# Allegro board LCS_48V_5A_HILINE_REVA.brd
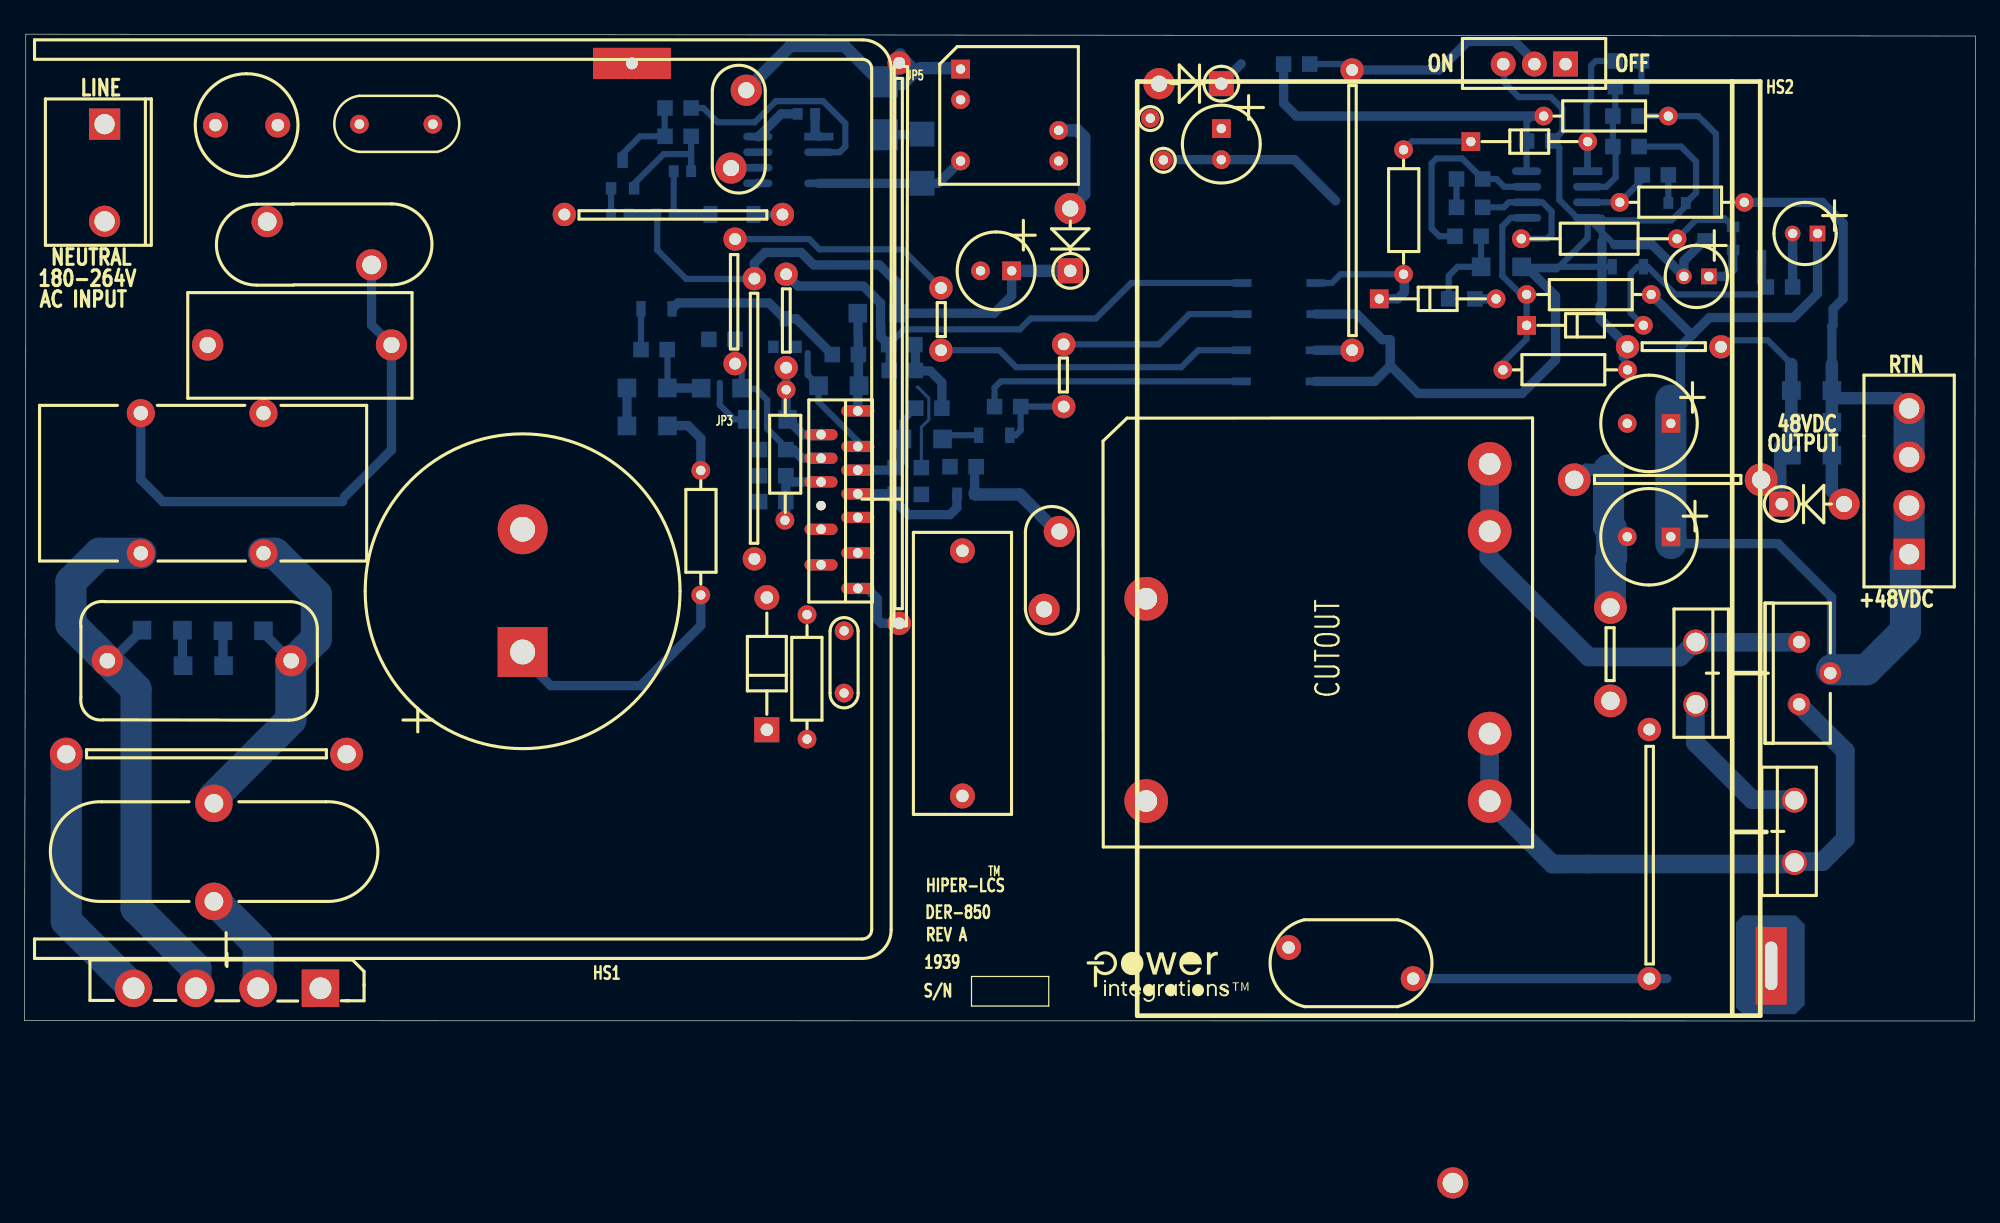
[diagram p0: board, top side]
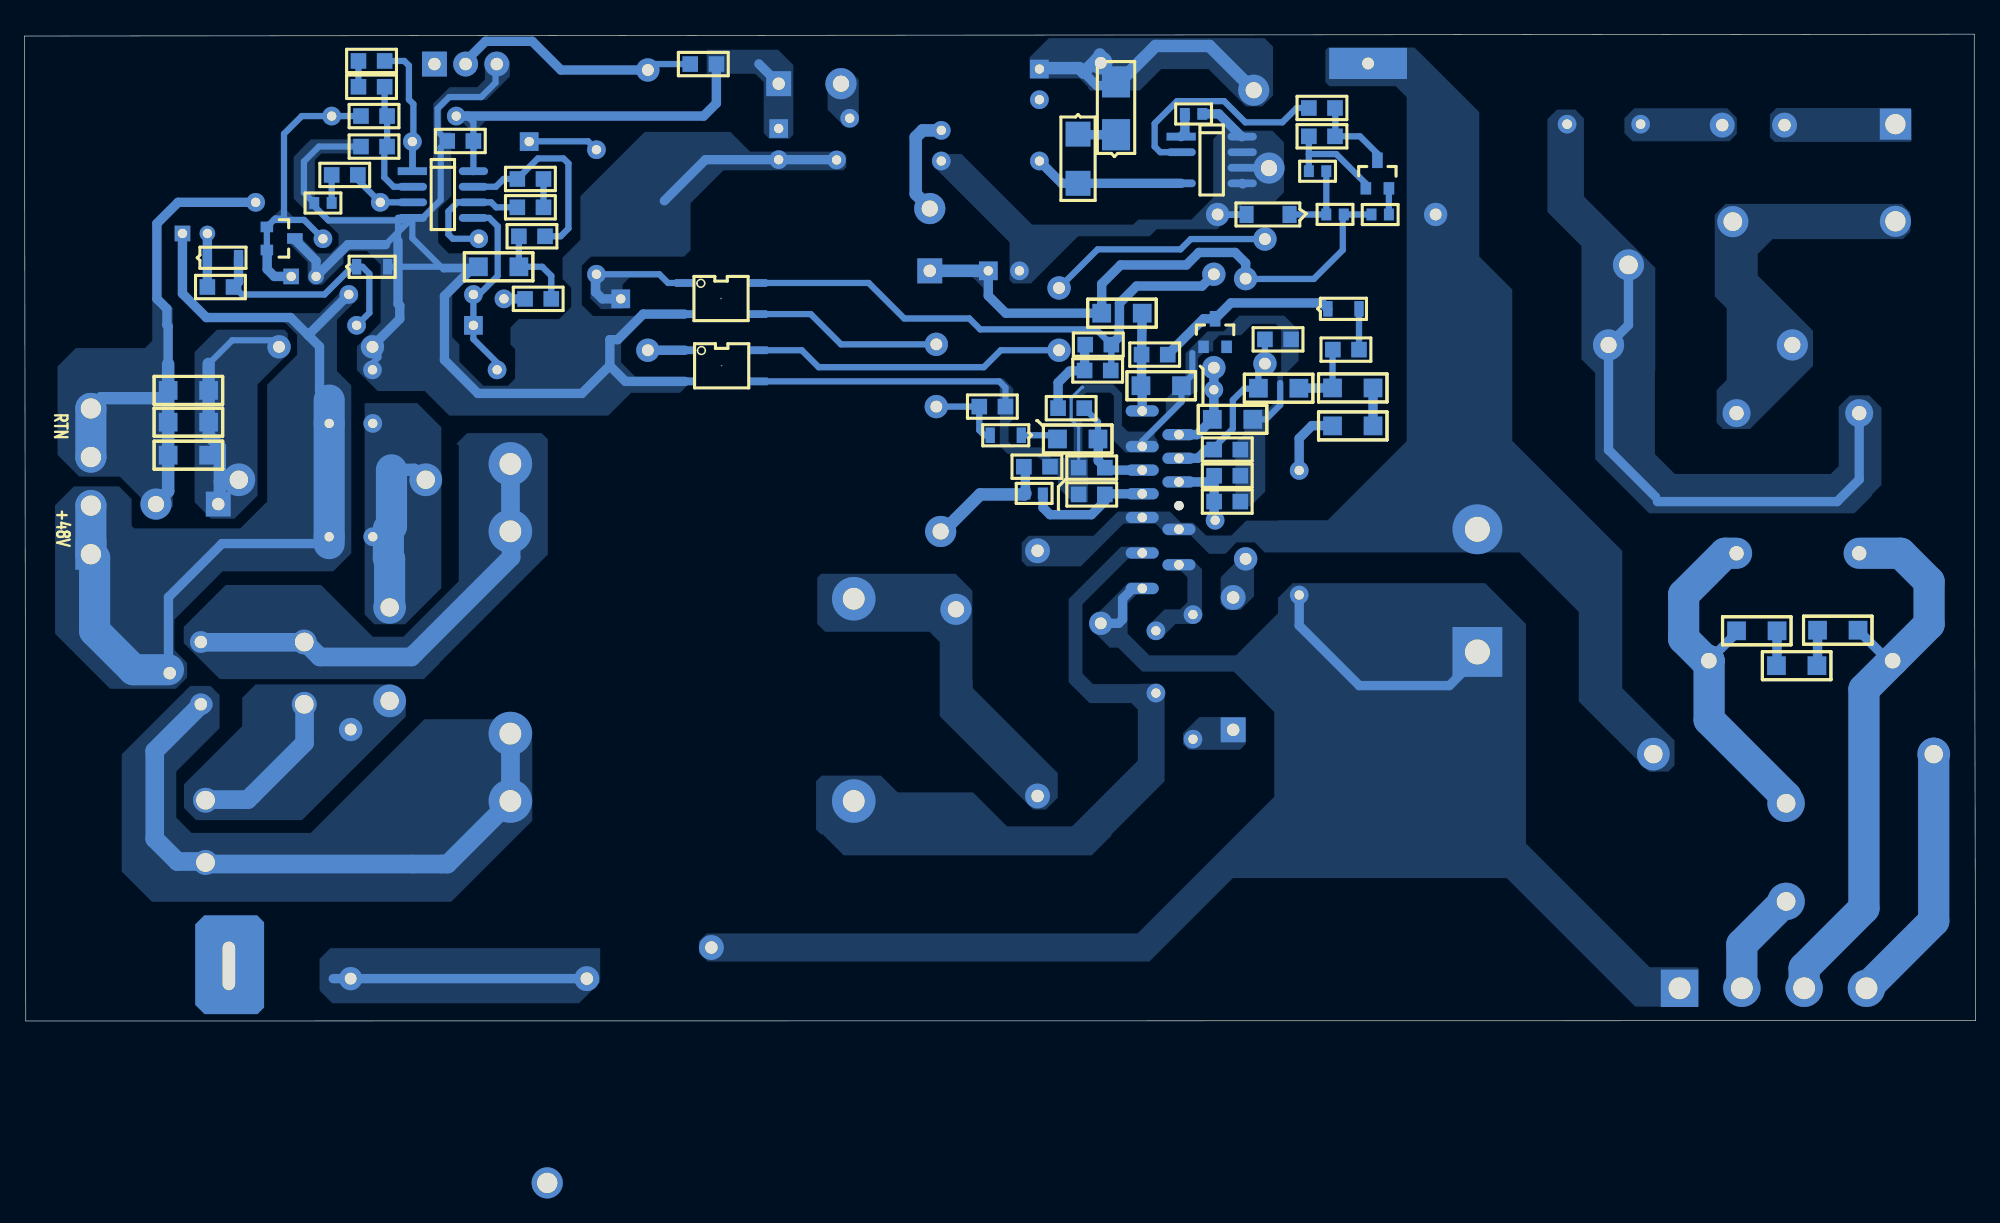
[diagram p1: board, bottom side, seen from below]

Outline 159.08 x 80.49 mm; copper layers: TOP, BOTTOM. Coordinates in mm from the lower left corner of the outline.
Outline path: 0,0.03 0.1,55.09 0.1,80.49 159.08,80.34 158.98,0 0,0.03

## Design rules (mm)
constraint set DEFAULT: min track width 0.508

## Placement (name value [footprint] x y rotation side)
BR1  GBU8J  [PIDAXBRIDGEGBU8]  24.13 2.67 180 top
C1  220 nF  [PINPXCAPRAD720X340590040]  29.92 55.14 180 top
C2  470 nF  [PINPCAPRAD760X380590050]  21.74 29.39 180 top
C3  270 uF  [PIPOLCAPCLYD948LS394080]  40.59 30.1 90 top
C6  330 nF  [PINPCAPRAD200X100200030]  66.83 31.83 270 top
C7  330 nF  [PISMC0805]  70.51 53.06 0 bottom
C8  22 nF  [PISMC0805]  62.08 46.61 180 bottom
C9  4.7 nF  [PISMC0805]  62.08 44.48 180 bottom
C10  1 uF  [PISMC1206]  62.23 49.07 180 bottom
C11  1 uF  [PISMC1206]  68.05 51.82 180 bottom
C12  4.7 nF  [PISMC0805]  70.99 45.14 0 bottom
C13  1 nF  [PISMC0805]  70.99 42.95 0 bottom
C14  0.039 uF  [PINPCAP23X8X20MMLSD040]  76.48 38.35 270 top
C15  47 pF  [PINPCAPRAD370X156250040]  84.4 39.93 270 top
C16  2.2 nF  [PINPYCAPRAD540X290LS400040]  103.07 5.99 0 top
C20  1.5 uF  [PISMC1206]  122.07 61.52 180 bottom
C21  150 nF  [PISMC0805]  118.9 68.68 180 bottom
C23  100 nF  [PISMC0805]  122.48 71.78 0 bottom
C24  22 nF  [PISMC0805]  131.85 76.2 180 bottom
C25  10 uF  [PIPOLCAPCLYD200LS80030]  137.34 60.73 180 top
C27  4.7 nF  [PINPCAPRAD370X156250040]  58.88 75.92 270 top
C28  1 uF  [PISMC0603]  64.47 73.99 180 bottom
C29  150 uF  [PIPOLCAPCYLD250LS100030]  97.59 72.8 270 top
C30  150 uF  [PIPOLCAPCYLD250LS100030]  80.49 61.19 180 top
C31  10 nF  [PISMC0805]  54.36 72.16 180 bottom
C35  27 uF  [PIPOLCAPCLYD320LS140030]  134.24 48.74 180 top
C37  68 nF  [PISMC0805]  134.04 69.01 180 bottom
C38  1 uF  [PIPOLCAPCLYD200LS80030]  146.2 64.24 180 top
C39  27 uF  [PIPOLCAPCLYD320LS140030]  134.24 39.5 180 top
D1  BAV19WS  [PISMSOD323]  77.8 47.78 0 bottom
D2  BAV19WS  [PISMSOD323]  52.81 58.09 180 bottom
D3  UF4005  [PIDAX475X125040DO41]  60.53 23.75 90 top
D6  1N4148  [PIDAX375X070030DO35]  117.93 71.73 0 top
D7  1N4148  [PIDAX375X070030DO35]  110.46 58.9 0 top
D8  1N4002-E3/54  [PIDV200X110X040DO41]  143.28 42.16 0 top
D9  UF4003  [PIDV200X110X040DO41]  97.59 76.45 180 top
D10  UF4003  [PIDV200X110X040DO41]  85.27 61.19 90 top
D11  US1J  [PISMDSMA]  73.18 72.34 270 bottom
D12  MBR2060CT  [PIDVTO2203VF1]  144.7 28.37 90 top
D13  MBR1060  [PIDVT0220ACREVA]  136.27 25.83 90 top
D14  MBR1060  [PIDVT0220ACREVA]  144.32 18.01 270 top
D15  BAV19WS  [PISMSOD323]  144.17 62.26 180 bottom
D16  BAV19WS  [PISMSOD323]  132 61.52 180 bottom
D17  1N4148  [PIDAX375X070030DO35]  122.48 56.74 0 top
F1  5 A  [PI_TR5_SUBMIN_FUSE]  15.57 73.08 0 top
HS1  HEATSINK, W/PEM NUT AND EYELET, PI CUST  [PI_HS_DER447_BRIDGE_ESIP]  0.81 80.04 270 top
HS2  HEATSINK,  FAB, DER850, PI CUST  [PI_HS_1P_DER850]  141.53 0.43 0 top
J1  CON3  [PI_HDR_3PIN_156_LOCK]  6.53 73.15 180 top
J2  CON4  [PI_HDR_4PIN]  153.67 38.07 0 top
J5  FL2  [PI_HOLE_30AWG]  92.86 70.23 0 top
J6  FL1  [PI_HOLE_30AWG]  91.8 73.63 0 top
JP1  J  [PI_JUMPER700]  44.02 65.79 0 top
JP2  J  [PI_JUMPER400]  57.94 53.62 90 top
JP3  J  [PI_JUMPER900]  59.51 60.55 270 top
JP4  J  [PI_JUMPER300]  62.1 60.91 270 top
JP5  J  [PI_JUMPER1800]  71.32 32.44 90 top
JP6  J  [PI_JUMPER200]  74.73 59.79 270 top
JP7  J  [PI_JUMPER200]  84.73 50.11 90 top
JP8  J  [PI_JUMPER900]  108.25 54.71 90 top
JP9  J  [PI_JUMPER300]  130.71 54.99 0 top
JP10  J  [PI_JUMPER600-18AWG-SLD]  126.36 44.15 0 top
JP11  J  [PI_JUMPER300-18AWG-SLD]  129.31 26.11 90 top
JP12  J  [PI_JUMPER800]  132.49 3.45 90 top
JP13  J  [PI_JUMPER900-18AWG-SLD]  3.4 21.77 0 top
L1  9 mH  [PI_IND_4P_500X1050LS450D46]  9.48 38.15 90 top
L2  100 uH  [PI2P455X1062LS315D60]  15.44 9.75 90 top
NOREF  -  []  0 0.03 0 top
NOREF#2  -  []  0 0.03 90 top
NOREF#3  -  []  -228.17 -156.46 0 top
NOREF#4  -  []  -150.35 42.55 0 top
NOREF#5  -  []  86.61 6.12 0 top
Q1  MMBT4403  [PISMSOT23132]  47.83 67.92 180 bottom
R1  680 k  [PISMR1206]  9.58 31.88 0 bottom
R2  680 k  [PISMR1206]  12.93 28.98 0 bottom
R3  680 k  [PISMR1206]  16.18 31.83 0 bottom
R4  301 k  [PI14WRESD100LS400D030]  55.14 44.91 270 top
R5  287 k  [PISMR1206]  52.43 48.54 180 bottom
R6  287 k  [PISMR1206]  49.12 51.64 0 bottom
R8  4.99 k  [PISMR0805]  52.4 54.76 180 bottom
R9  10.0 k  [PISMR1206]  55.17 51.61 0 bottom
R10  10 k  [PISMR0805]  57.94 55.6 180 bottom
R11  3.3 k  [PISMR0805]  65.86 54.36 0 bottom
R12  82.5 k  [PISMR0805]  70.46 55.17 0 bottom
R13  5.76 k  [PISMR0805]  74.8 49.99 180 bottom
R14  2.2 k  [PISMR1206]  74.85 47.47 180 bottom
R15  4.7 k  [PISMR0805]  81.23 50.11 180 bottom
R16  6.81 k  [PI14WRESD100LS400D030#2]  62 53.54 270 top
R17  130 k  [PISMR0805]  62.08 42.37 180 bottom
R18  4.7  [PISMR1206]  71.25 57.73 180 bottom
R19  2.2  [PI14WRESD100LS400D030]  63.8 22.99 90 top
R20  220  [PISMR0603]  76.05 43.03 0 bottom
R21  39  [PISMR0805]  75.46 45.21 0 bottom
R22  1 k  [PISMR0805]  118.26 58.9 180 bottom
R23  1.3 k  [PI14WRESD100LS400D030]  112.45 71.07 270 top
R24  182 k  [PI14WRESD100LS500D030#2]  132.64 59.26 180 top
R26  10 k  [PISMR0805]  116.76 66.37 0 bottom
R27  10.0 k  [PI14WRESD100LS400D030]  120.55 53.11 0 top
R28  22 k  [PI14WRESD100LS500D030]  134.75 63.8 180 top
R29  3.3 k  [PI14WVRESD100LS100D030]  123.88 73.81 0 top
R30  22 k  [PISMR0805]  129.72 78.31 0 bottom
R31  249 k  [PISMR0805]  129.51 73.81 0 bottom
R32  5.11 k  [PISMR0805]  129.51 71.32 0 bottom
R33  5.1 k  [PI14WRESD100LS400D030]  130.07 66.78 0 top
R34  0.03  [PISMR1206]  144.07 46.15 0 bottom
R35  0.03  [PISMR1206]  144.07 51.43 0 bottom
R36  100  [PISMR0603]  49.25 65.79 180 bottom
R37  1 k  [PISMR0603]  51.51 65.79 0 bottom
R38  15 k  [PISMR0805]  52.22 74.47 0 bottom
R39  10 k  [PISMR0805]  102.67 78.05 0 bottom
R40  1 k  [PISMR0603]  54.36 69.32 180 bottom
R42  0.03  [PISMR1206]  144.07 48.84 0 bottom
R43  1 k  [PISMR0805]  118.77 64.01 180 bottom
R44  510  [PISMR0603]  135.46 66.73 180 bottom
R45  100 k  [PISMR0805]  144.17 59.87 180 bottom
RT1  2.5  [PI_RAD180X395LS235D031]  27.3 73.15 0 top
RV1  320 Vac  [PIDISC675X225LS335X140040]  28.3 61.67 180 top
SW1  SPDT SLIDE  [PI_SWITCH_SPDT_SLIDE_PCBM_1]  125.65 78.05 90 top
T1  ETD34  [PI_XFRMR_DER850_LLC]  91.44 45.47 0 top
T2  EE10  [PI_XFRMR_DER850_BIAS]  76.33 77.65 0 top
U1  LCS708HG  [PI_IC_ESIP16-13_OVAL_SLOT]  67.94 49.76 270 top
U2  LNK302D  [PISMSO8DNSHORT5678]  64.77 72.14 270 bottom
U3  LM431AIM3  [PISMSOT23123]  139.32 62.89 270 bottom
U4  PC357A  [PI_4_SMD]  102.29 58.93 270 bottom
U5  LM358D  [PISMSO8]  127.46 69.32 270 bottom
U6  PC357A  [PI_4_SMD]  102.23 53.44 270 bottom
VR1  BZX84C5V1LT1G  [PISMSOT23123]  61.06 54.99 180 bottom
VR2  MMSZ5242B-7-F  [PI_SM_SOD-123_12]  55.93 65.79 0 bottom
VR3  SMAJ150A-13-F  [PISMDO214AC12]  70.08 72.29 90 bottom

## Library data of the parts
BR1 = DISCRETE BRIDGE_+~~-
C1 C6-C8 C10 C11 C14 C20 C21 C23 C24 C27 C28 C37 = CAP NP
C2 = CAP NP: tolerance: 20
C3 C35 C39 = CAP POL
C9 C12 C13 C31 = CAP NP: tolerance: 10
C15 = CAP NP: tolerance: 5
C16 = CAP NP: alternate symbols: (pinpycaprad540x290ls400040h)
C25 C38 = CAP POL: alternate symbols: (pipolcapclyd200ls80030h)
C29 C30 = CAP POL: tolerance: 20
D1 D2 D11 D15 D16 = DIODE
D3 = DIODE: alternate symbols: (pidax475x125040do41,pidax390x125040do41)
D6 D7 D17 = DIODE: alternate symbols: (pidax375x070030do35,pidv100x080x030do35)
D8-D10 = DIODE: alternate symbols: (pidax475x125040do41,pidv200x110x040do41wbead,pidax390x125040do41)
D12 = DS_DUAL_CK_A_AC: alternate symbols: (pidvto2203)
D13 D14 = DIODE SCHOTTKY
F1 = FUSE
HS1 = HS-PI_CUSTOM1
HS2 = hs_1P_DER850
J1 = CON3
J2 = CON4
J5 J6 = TERM_1Pin
JP1-JP13 = JUMPER_1
L1 = INDUCTOR_4P_REVB_0
L2 = INDUCTOR
Q1 = PNP_BEC
R1-R3 R10-R14 R17 R18 R20-R22 R26 R30-R32 R34-R40 R42 R43 R45 = R
R4 R19 R23 R28 = R: alternate symbols: (pi14wvresd100ls125d030,pi14wvresd100ls150d030,pi14wvresd100ls200d030,pi14wvresd100ls300d030,pi14wresd100ls400d030,pi14wresd100ls500d030)
R5 R6 R8 R9 R44 = R: tolerance: 1%
R15 = R: tolerance: 5%
R16 R24 R27 R29 = R: alternate symbols: (pi14wvresd100ls200d030,pi14wresd100ls400d030,pi14wresd100ls500d030)
R33 = R: alternate symbols: (pi14wvresd100ls125d030,pi14wvresd100ls150d030,pi14wvresd100ls200d030,pi14wvresd100ls300d030,pi14wresd100ls400d030,pi14wresd100ls500d030); tolerance: 1%
RT1 = THERMISTOR
RV1 = VARISTOR
SW1 = SW SLIDE-SPDT
T1 = BETD_34_DER850_LLC
T2 = BEE_10_DER850_Bias
U1 = LC_SWITCH_Rev03: alternate symbols: (pi_ic_esip16-13_socket_sl0t,pi_ic_esip16-13_oval_slot)
U2 = LNK30X_SO8_DN
U3 = TL431/SOT-23_CAR: tolerance: 2%
U4 U6 = OPTO_A_B
U5 = LM358
VR1 = DIODE_ZENERC2A1
VR2 VR3 = DIODE_ZENER

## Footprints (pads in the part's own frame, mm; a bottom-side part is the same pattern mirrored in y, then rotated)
PI2P455X1062LS315D60
  round 3.048 hole 1.524: 1(0,0) 2(8.001,0)
PI14WRESD100LS400D030
  round 1.524 hole 0.762: 1(0,0) 2(10.16,0)
PI14WRESD100LS400D030#2
  round 1.524 hole 0.762: 1(2.057,0.102) 2(12.7,0)
PI14WRESD100LS500D030
  round 1.524 hole 0.762: 1(0,0) 2(12.7,0)
PI14WRESD100LS500D030#2
  round 1.524 hole 0.762: 1(0,0) 2(10.16,0)
PI14WVRESD100LS100D030
  round 1.524 hole 0.762: 1(0,0) 2(10.16,0)
PI_4_SMD
  rect 0.635x1.524 smd: 1(-1.27,-2.997) 2(1.27,-2.997) 3(1.27,2.997) 4(-1.27,2.997)
PI_HDR_3PIN_156_LOCK
  rect 2.54x2.54 hole 1.651: 1(0,0)
  round 2.54 hole 1.651: 2(-109.931,86.36) 3(0,7.925)
PI_HDR_4PIN
  rect 2.54x2.54 hole 1.651: 1(0,0)
  round 2.54 hole 1.651: 2(0,3.962) 3(0,7.925) 4(0,11.887)
PI_HOLE_30AWG
  round 1.524 hole 0.762: 1(0,0)
PI_HS_1P_DER850
  rect 2.54x6.35 hole 1.016x3.962: 1(0.889,4.064)
PI_HS_DER447_BRIDGE_ESIP
  rect 2.54x6.35 hole 0.965: 1(1.93,48.717)
PI_IC_ESIP16-13_OVAL_SLOT
  oval 0.914x2.692 hole 0.787: 1(0,0) 3(1.93,-2.997) 4(2.896,0) 5(3.861,-2.997) 6(4.826,0) 7(5.791,-2.997) 8(6.756,0) 10(8.687,0) 11(9.652,-2.997) 13(11.582,0) 14(12.548,-2.997) 16(14.478,0)
  round 0.762 hole 0.762: 9(7.722,-2.997)
PI_IND_4P_500X1050LS450D46
  round 2.286 hole 1.168: 1(0,0) 2(11.43,-10) 3(11.43,0) 4(0,-10)
PI_JUMPER200
  round 1.905 hole 0.965: 1(0,0) 2(5.08,0)
PI_JUMPER300
  round 1.905 hole 0.965: 1(0,0) 2(7.62,0)
PI_JUMPER300-18AWG-SLD
  round 2.667 hole 1.499: 1(0,0) 2(7.62,0)
PI_JUMPER400
  round 1.905 hole 0.965: 1(0,0) 2(10.16,0)
PI_JUMPER600-18AWG-SLD
  round 2.667 hole 1.499: 1(0,0) 2(15.24,0)
PI_JUMPER700
  round 1.905 hole 0.965: 1(0,0) 2(17.78,0)
PI_JUMPER800
  round 1.905 hole 0.965: 1(0,0) 2(20.32,0)
PI_JUMPER900
  round 1.905 hole 0.965: 1(0,0) 2(22.86,0)
PI_JUMPER900-18AWG-SLD
  round 2.667 hole 1.499: 1(0,0) 2(22.86,0)
PI_JUMPER1800
  round 1.905 hole 0.965: 1(0,0) 2(45.72,0)
PI_RAD180X395LS235D031
  round 1.524 hole 0.787: 1(0,0) 2(5.994,0)
PI_SM_SOD-123_12
  rect 1.143x1.397 smd: 1(0,0) 2(3.505,0)
PI_SWITCH_SPDT_SLIDE_PCBM_1
  rect 2.032x2.032 hole 1.016: 1(0,0)
  round 2.032 hole 1.016: 2(0,2.54) 3(0,5.08)
PI_TR5_SUBMIN_FUSE
  round 2.032 hole 1.016: 1(0,0) 2(5.08,0)
PI_XFRMR_DER850_BIAS
  rect 1.524x1.524 hole 0.762: 1(0,0)
  round 1.524 hole 0.762: 2(0,-2.499) 4(0,-7.501) 5(8.001,-7.501) 6(8.001,-5.001)
PI_XFRMR_DER850_LLC
  round 3.556 hole 1.778: 3(0.025,-11.026) 6(0.025,-27.526) 7(28.026,-27.526) 8(28.026,-22.024) 11(28.026,-5.524) 12(28.026,-0.025)
PIDAX375X070030DO35
  rect 1.524x1.524 hole 0.762: 1(0,0)
  round 1.524 hole 0.762: 2(9.525,0)
PIDAX475X125040DO41
  rect 2.032x2.032 hole 1.016: 1(0,0)
  round 2.032 hole 1.016: 2(10.795,0)
PIDAXBRIDGEGBU8
  rect 3.048x3.048 hole 1.778: 1(0,0)
  round 3.048 hole 1.778: 2(5.08,0) 3(10.16,0) 4(15.24,0)
PIDISC675X225LS335X140040
  round 2.54 hole 1.524: 1(0,0) 2(8.509,-3.531)
PIDV200X110X040DO41
  rect 2.032x2.032 hole 1.016: 1(0,0)
  round 2.54 hole 1.321: 2(5.08,0)
PIDVT0220ACREVA
  round 2.032 hole 1.524: 1(5.08,0) 2(0,0)
PIDVTO2203VF1
  round 1.778 hole 1.016: 1(-2.54,0) 2(0,-2.54) 3(2.54,0)
PINPCAP23X8X20MMLSD040
  round 2.032 hole 1.016: 1(0,0) 2(20,0)
PINPCAPRAD200X100200030
  round 1.524 hole 0.762: 1(0,0) 2(5.08,0)
PINPCAPRAD370X156250040
  round 2.54 hole 1.321: 1(0,-0.025) 2(6.35,-1.27)
PINPCAPRAD760X380590050
  round 2.54 hole 1.27: 1(0,0) 2(14.986,0)
PINPXCAPRAD720X340590040
  round 2.54 hole 1.321: 1(0,0) 2(14.986,0)
PINPYCAPRAD540X290LS400040
  round 2.032 hole 1.016: 1(0,0) 2(10.16,-2.54)
PIPOLCAPCLYD200LS80030
  rect 1.27x1.27 hole 0.762: 1(0,0)
  round 1.27 hole 0.762: 2(2.032,0)
PIPOLCAPCLYD320LS140030
  rect 1.524x1.524 hole 0.762: 1(0,0)
  round 1.524 hole 0.762: 2(3.556,0)
PIPOLCAPCLYD948LS394080
  rect 4.064x4.064 hole 2.032: 1(0,-0.025)
  round 4.064 hole 2.032: 2(10.008,-0.025)
PIPOLCAPCYLD250LS100030
  rect 1.524x1.524 hole 0.762: 1(0,0)
  round 1.524 hole 0.762: 2(2.54,0)
PISMC0603
  rect 0.813x0.965 smd: 1(0,0) 2(1.422,0)
PISMC0805
  rect 1.27x1.27 smd: 1(0,0) 2(2.134,0)
PISMC1206
  rect 1.524x1.524 smd: 1(0,0) 2(3.302,0)
PISMDO214AC12
  rect 2.54x2.286 smd: 1(0,0) 2(4.318,0)
PISMDSMA
  rect 2.032x2.032 smd: 1(0,0) 2(4.013,0)
PISMR0603
  rect 0.813x0.965 smd: 1(0,0) 2(1.422,0)
PISMR0805
  rect 1.27x1.27 smd: 1(0,0) 2(2.134,0)
PISMR1206
  rect 1.524x1.524 smd: 1(0,0) 2(3.302,0)
PISMSO8
  rect 0.635x2.388 smd: 1(0,0)
  oval 0.635x2.388 smd: 2(1.27,0) 3(2.54,0) 4(3.81,0) 5(3.81,4.978) 6(2.54,4.978) 7(1.27,4.978) 8(0,4.978)
PISMSO8DNSHORT5678
  rect 0.635x2.388 smd: 1(0,0)
  oval 0.635x2.388 smd: 2(1.27,0) 4(3.81,0) 5(3.81,4.978) 6(2.54,4.978) 7(1.27,4.978) 8(0,4.978)
PISMSOD323
  rect 0.762x1.27 smd: 1(0,0) 2(2.54,0)
PISMSOT23123
  rect 0.864x1.016 smd: 1(-1.88,0) 3(0,0)
  rect 0.864x1.27 smd: 2(-0.94,2.286)
PISMSOT23132
  rect 0.864x1.016 smd: 1(-1.88,0) 2(0,0)
  rect 0.864x1.27 smd: 3(-0.94,2.286)

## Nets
VCC: C23.1 C29.1 D9.1 R29.1 R39.1 U5.8
VCCPR: C30.1 D10.1 JP3.1 R18.1 R36.1 R37.1
B+: BR1.1 C3.1 C16.1 JP5.1 R4.2 U1.16
SOURCE: C27.2 C28.2 C30.2 JP1.2 T2.5 U2.5(S) U2.6 U2.7 U2.8 VR2.2
N5956875: C11.1 R11.2 R18.2 U1.1
N5956925: C8.2 C9.2 C10.2 C11.2 C12.2 C13.2 R10.2 R15.2 R17.2 R21.1 U1.4 U6.3(E) VR1.1
N5956929: C10.1 JP4.2 R16.1 U1.3(VREF)
N5957241: D3.1 R19.1
N6197642: C7.2 R12.2 R13.1
N6214944: C6.1 R19.2 U1.14
N6216380: D3.2 JP3.2
N6234122: C9.1 R16.2 R17.1 U1.7
N6240208: R6.2 R8.1 R9.1
N6267022: C12.1 R13.2 R14.2 U1.6
N6283849: C14.2 C15.2 T1.3
N6289562: C7.1 JP4.1 R12.1 U4.4
N6938702: C15.1 R20.2 R21.2
N6939237: C6.2 T1.6 U1.13
N7091362: C35.1 C38.1 C39.1 D12.2(K) J2.1 J2.2 R24.1
N7093005: D8.2 J2.3 J2.4 R33.2 R34.2 R35.2 R42.2
N7953071: R5.2 R6.1
N8059193: C1.1 L1.3 RT1.2 RV1.1
N8059197: F1.1 J1.1
N8059233: C2.1 L1.4 L2.2 R3.2
N8059379: R1.2 R2.1
N8059437: C1.2 J1.3 L1.2 RV1.2
N8059489: BR1.3(AC2) C2.2 L1.1 R1.1
N8070264: D6.1 R23.1
N8070276: C25.1 R28.1 R29.2 R31.2 U3.1 U3.3(VREF)
N8070304: C21.1 R43.2 U5.7(OUT)
N8070334: D17.1 R24.2 R27.1 U5.5
N8070354: C20.1 C23.2 C25.2 C29.2 D16.2 J5.1 JP9.1 R27.2 R32.2 R44.1 SW1.3 U3.2 U4.2 U5.4 U6.2
N8070466: R26.2 R28.2 U5.6
N8070490: D6.2 R30.1 U5.1
N8070648: C24.2 R31.1 R32.1 U5.2
N8073568: C3.2 C14.1 HS1.1 JP1.1 JP13.2 U1.10 U1.11
N8075340: C13.1 R20.1 U1.8
N8076366: C8.1 JP2.1 R9.2 R10.1 U1.5
N8076448: C16.2 JP12.1
N8079055: D7.1 R23.2 U4.1
N8088388: F1.2 RT1.1
N8091793: D2.2 R8.2
N8091974: D2.1 R11.1 VR1.2
N8094723: R37.2 R40.2 VR2.1
N8094759: C31.2 Q1.3 R38.1
N8094763: R38.2 U2.2
N8095081: Q1.2(EMITTER) R36.2
N8095089: C28.1 U2.1
N8095536: D11.2 T2.4 U2.4
N8096951: C31.1 Q1.1 R40.1
N8097697: D9.2 J6.1
N8106560: D1.2 JP7.1 R15.1
N8123728: D8.1 JP9.2 JP10.2 R34.1 R35.1 R42.1
N8130547: JP8.2 R39.2 SW1.2
N8131154: JP8.1 U6.1
N8135210: C24.1 R30.2
N8181225: R4.1 R5.1
N8231213: BR1.2 L2.1
N8233629: D12.1 D14.1 T1.7 T1.8
N8233891: D13.2 D14.2 JP11.1 JP12.2
N8234616: D12.3 D13.1 T1.11 T1.12
N8234966: C35.2 C39.2 JP10.1 JP11.2
N8241021: C37.2 R33.1 U5.3
N8243259: C20.2 R22.2 R43.1
N8254175: C27.1 JP5.2 T2.1 VR3.2
N8276702: R2.2 R3.1
N8291038: C38.2 D15.1 R45.1
N8291055: D15.2 D16.1 D17.2 R45.2
N8302888: JP7.2 U4.3(E)
N8302918: D1.1 R14.1
N8303536: JP6.2 U6.4
N8303591: JP2.2 JP6.1
N8304521: BR1.4 JP13.1
N8305228: C37.1 R44.2
N8311567: C21.2 R26.1
N8322201: D10.2 T2.6
N80706600: D7.2 R22.1
N82138101: D11.1 VR3.1

Pads without a net: HS2 1; J1 2; SW1 1; T2 2; U1 9; VR1 3

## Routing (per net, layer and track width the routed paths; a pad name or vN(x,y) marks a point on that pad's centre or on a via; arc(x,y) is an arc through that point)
VCC: length 31.9
  BOTTOM w0.508: 122.99,73.81 122.48,73.3 C23.1 U5.8 122.48,69.24
  BOTTOM w0.762: 99.2,78.07 D9.1 ; R29.1 103.71,73.81 102.67,74.85 R39.1
VCCPR: length 48.1
  BOTTOM w0.508: JP3.1 59.74,60.55 59.77,60.53 53.95,60.53 51.59,62.89 51.59,65.79 R37.1 R36.1
  BOTTOM w0.762: C30.1 80.49,59.16 79.07,57.73 R18.1 71.25,60.12 69.7,61.67 64.34,61.67 63.32,62.69 60.37,62.69 59.51,61.83 JP3.1
  BOTTOM w1.016: D10.1 C30.1
B+: length 26
  BOTTOM w0.762: R4.2 55.14,32.26 50.24,27.36 42.9,27.36 40.61,29.64 C3.1 ; U1.16 68.71,35.28 69.55,34.44 69.55,32.75 69.86,32.44 JP5.1
SOURCE: length 8.9
  BOTTOM w0.508: JP1.2 61.77,65.76 59.41,65.76 VR2.2 JP1.2 ; JP1.2 61.82,65.81
  BOTTOM w0.762: C28.2 61.7,73.99 59.84,72.14 U2.8 ; 59.74,68.28 U2.5
N5956875: length 8
  BOTTOM w0.762: R18.2 R11.2 68,51.87 C11.1 67.94,51.71 U1.1
N5956925: length 43
  BOTTOM w0.254: C12.2 73.13,48.44 73.74,49.05 73.74,50.8 72.85,51.69 72.8,51.69
  BOTTOM w0.508: 56.69,52.04 56.69,50.24 57.86,49.07 C10.2 ; U6.3 79.6,52.17 79.1,51.66 R15.2 79.07,50.09 ; U1.4 67.94,47.29 64.74,50.5 C11.2 63.86,52.7 63.86,54.48
N5956929: length 7.5
  BOTTOM w0.762: U1.3 63.47,47.83 C10.1 62.1,49.2 JP4.2
N6197642: length 6.8
  BOTTOM w0.762: R13.1 74.8,52.07 73.86,53.01 C7.2 72.64,55.12 R12.2
N6234122: length 6.7
  BOTTOM w0.762: R16.2 62.08,40.92 R17.1 C9.1 62.59,43.97 U1.7
N6240208: length 5.9
  BOTTOM w0.508: R6.2 52.43,54.74 R8.1
  BOTTOM w0.762: R6.2 R9.1
N6267022: length 8.7
  BOTTOM w0.508: R14.2 71.55,48.87 R13.2 72.69,50.01
  BOTTOM w0.762: U1.6 70.79,44.93 C12.1 70.99,45.16 71.53,45.69 71.53,47.45 R14.2
N6289562: length 45.4
  BOTTOM w0.508: C7.1 70.46,53.11 R12.1 71.7,56.41 81.15,56.41 82.04,57.3 87.35,57.3 90.25,60.2 U4.4
  BOTTOM w0.762: R12.1 69.82,55.8 69.82,56.64 69.8,56.67 69.8,58.55 68.4,59.94 63.07,59.94 JP4.1
N6938702: length 10.4
  BOTTOM w0.508: 84.18,39.93 C15.1
  BOTTOM w0.762: R21.2 77.47,45.09 R20.2
  BOTTOM w1.016: R20.2 77.55,42.95 81.15,42.95 84.18,39.93
N7091362: length 77.5
  BOTTOM w0.762: R24.1 135.95,55.94 ; 135.95,55.94 135.03,55.02 135.03,51.41 134.26,50.65 134.24,50.65 ; 135.95,55.94 137.39,57.38 144.25,57.38 146.2,59.33 C38.1 ; 147.35,28.65 147.35,34.57 142.98,38.94 134.24,38.94
  BOTTOM w2.54: 147.35,28.65 150.19,28.65 153.37,31.83 153.37,37.77 J2.1 J2.2 ; 134.24,38.94 C39.1 C35.1 134.24,50.65
N7093005: length 42.8
  BOTTOM w0.762: 147.37,53.59 147.37,56.67 147.47,56.77 147.47,58.09 148.29,58.9 148.29,65.05 146.56,66.78 R33.2
  BOTTOM w1.016: 147.37,50.8 R35.2 147.37,53.59 ; 147.37,50.8 152.83,50.8 J2.4 ; 147.37,50.8 R42.2 R34.2 147.37,43.21 148.23,42.34
  BOTTOM w2.54: J2.4 J2.3
N7953071: length 3.1
  BOTTOM w0.762: R6.1 R5.2
N8059193: length 43.8
  BOTTOM w0.762: 25.93,42.37 11.28,42.37 9.48,44.16 L1.3 ; RV1.1 28.3,56.77 C1.1 29.92,46.58 26.09,42.75
N8059233: length 29.7
  BOTTOM w0.762: R3.2 19.48,31.65 C2.1
  BOTTOM w2.54: L2.2 15.44,18.29 21.72,24.56 21.72,29.36 C2.1 22,29.39 23.79,31.19 23.79,34.78 20.42,38.15 L1.4
N8059379: length 2.9
  BOTTOM w0.762: R1.2 12.88,29.03 R2.1
N8059489: length 47.9
  BOTTOM w0.762: R1.1 7.09,29.39 C2.2
  BOTTOM w2.54: L1.1 6.1,38.15 3.78,35.84 3.78,32.36 C2.2 9.09,27.05 9.09,9.19 13.97,4.32 BR1.3
N8070264: length 5.8
  BOTTOM w0.508: D6.1 117.91,71.76 113.13,71.76 R23.1
N8070276: length 25.7
  BOTTOM w0.508: R28.1 136.28,65.34 138.75,65.34 ; 138.75,65.34 138.63,65.46 137.95,65.46 137.92,65.48 137.92,72.36 136.47,73.81 R29.2 R31.2 ; 138.75,65.34 U3.1 U3.3
  BOTTOM w0.762: C25.1 138.71,60.73 139.29,61.32 139.29,62.86 U3.3
N8070304: length 16.3
  BOTTOM w0.508: U5.7 120.65,68.05 120.02,68.68 C21.1 117.22,70.36 115.14,70.36 114.73,69.95 114.73,64.64 115.37,64.01 R43.2
N8070334: length 15.3
  BOTTOM w0.508: U5.5 121.18,65.51 120.5,64.82 120.5,60.78 122.02,59.26 R24.2 D17.1 122.48,55.63 120.52,53.67
N8070354: length 132.7
  BOTTOM w0.508: 122.86,61.32 124.92,61.32 127.46,63.86 U5.4 ; 127.66,65.3 U5.4 ; 127.66,65.3 134.29,65.3 135.46,66.47 R44.1 136.3,67.56 136.3,70.1 135.08,71.32 R32.2 ; 127.66,65.3 129.64,63.32 ; U5.4 128.63,65.51 128.63,63.63 ; U5.4 126.61,65.51 125.15,66.97 125.15,71.25 C23.2 125.4,72.57 125.4,74.42 124.46,75.36 121.84,75.36 120.68,76.53 120.68,77.95 SW1.3 ; 130.68,53.67 130.23,54.13 130.23,55.52 ; C20.1 D16.2
  BOTTOM w0.762: 111.37,53.45 111.35,53.47 111.35,55.58 110.72,55.58 108.64,57.66 U4.2 ; 111.37,53.45 110.08,52.17 U6.2 ; 111.37,53.45 113.63,51.19 122.11,51.19 124.84,53.92 124.84,59.13 122.86,61.11 122.86,61.32 ; 130.23,55.52 128.48,57.27 128.48,58.35 128.63,58.5 128.63,63.63 ; U3.2 137.03,63.73 135.31,62 C25.2 132.72,63.32 129.64,63.32 ; 106.91,66.9 103.56,70.26 C29.2 92.89,70.26 J5.1
N8070466: length 10.6
  BOTTOM w0.508: 122.45,66.8 U5.6 ; U5.6 123.77,66.78 124.52,66.03 124.52,64.17 124.16,63.8 R28.2 ; U5.6 121.03,66.78 120.62,66.37 R26.2
N8070490: length 13.3
  BOTTOM w0.508: D6.2 U5.1 127.43,69.34 127.43,71.07 127.37,71.13 127.37,74.8 127.74,75.16 127.74,77.93 128.12,78.31 R30.1
N8070648: length 10.2
  BOTTOM w0.508: C24.2 129.72,74.02 R31.1 R32.1 129.74,71.09 129.74,68.81 128.98,68.05 U5.2
N8075340: length 10.5
  BOTTOM w0.762: U1.8 70.94,43 C13.1 70.99,42.39 72.09,41.3 75.46,41.3 76.02,41.86 76.02,43 R20.1
N8076366: length 14.5
  BOTTOM w0.508: R10.1 JP2.1 57.91,53.59 58.47,53.04 R9.2 59.64,51.56 60.55,50.65 60.55,48.31 62.08,46.79 C8.1
  BOTTOM w0.762: U1.5 63.4,45.9 62.69,46.61 C8.1
N8076448: length 20.7
  BOTTOM w0.762: 113.23,3.45 JP12.1 133.91,3.45
N8079055: length 10.6
  BOTTOM w0.508: R23.2 107.31,60.91 106.6,60.2 U4.1
  BOTTOM w0.762: R23.2 112.5,60.85 112.5,59.44 111.96,58.9 111.12,58.9
N8091793: length 3.3
  BOTTOM w0.508: D2.2 R8.2
N8091974: length 15
  BOTTOM w0.762: D2.1 53.29,58.57 60.71,58.57 VR1.2 62.94,57.28 R11.1
N8094723: length 6.6
  BOTTOM w0.508: VR2.1 R37.2 R40.2 52.93,69.34
N8094759: length 6.9
  BOTTOM w0.508: 52.2,72.21 52.22,72.19 C31.2 ; 52.2,72.21 52.15,72.16 50.19,72.16 48.77,70.74 Q1.3 ; 52.2,72.21 52.2,74.45 R38.1
N8094763: length 18.8
  BOTTOM w0.508: U2.2 66.47,70.87 66.93,71.32 66.93,73.21 65.11,75.03 61.26,75.03 59.54,73.3 56.52,73.3 55.35,74.47 R38.2 54.33,74.5
N8095081: length 2.2
  BOTTOM w0.508: R36.2 Q1.2 47.83,67.95
N8095089: length 2
  BOTTOM w0.762: U2.1 64.47,72.44 C28.1
N8095536: length 12.3
  BOTTOM w0.762: T2.4 74.51,68.33 D11.2 U2.4
N8096951: length 8.9
  BOTTOM w0.508: 54.36,70.71 52.12,70.71 49.71,68.3 Q1.1 ; 54.36,70.71 C31.1 54.36,72.21 ; 54.36,70.71 R40.1
N8106560: length 6.5
  BOTTOM w0.508: 84.76,50.11 JP7.1 R15.1 81.23,48.18 80.82,47.78 D1.2
N8123728: length 21.6
  BOTTOM w0.508: 138.48,55.52 142.14,55.52 144.07,53.59
  BOTTOM w0.762: 143.15,46.84 143.08,46.76 143.08,44.88
  BOTTOM w1.016: 141.71,44.42 142.14,43.99 143.15,43.99 ; 143.15,43.99 143.15,42.34 ; 143.15,43.99 143.15,46.84 144.07,47.75 R42.1 R35.1 144.07,53.59
N8130547: length 20.4
  BOTTOM w0.508: JP8.2 107.77,78.05 R39.2
  BOTTOM w0.762: SW1.2 123.11,78.28 121.49,79.91 117.68,79.91 115.34,77.57 JP8.2
N8131154: length 3.3
  BOTTOM w0.762: U6.1 JP8.1 108.53,54.71
N8135210: length 2.1
  BOTTOM w0.508: R30.2 C24.1
N8181225: length 5.8
  BOTTOM w0.762: R5.1 52.45,48.56 54.1,48.56 55.14,47.52 R4.1
N8231213: length 8.6
  BOTTOM w2.54: L2.1 15.54,9.75 19.05,6.25 BR1.2
N8233629: length 50.3
  BOTTOM w1.524: 119.46,23.57 119.46,17.93 124.59,12.8 144.2,12.8 D14.1 144.4,13 146.61,13 148.46,14.86 148.46,22.02 144.65,25.83 144.5,25.83
N8233891: length 13.2
  BOTTOM w1.524: 136.25,25.91 136.25,22.68 140.87,18.06 144.27,18.06
N8234616: length 37
  BOTTOM w1.524: 144.78,30.91 144.75,30.89 136.19,30.89 135,29.69 127.53,29.69 119.41,37.82 119.41,39.9 119.46,39.95 119.46,45.59
N8234966: length 14
  BOTTOM w1.016: 129.16,44.96 127.3,44.96 126.77,44.42
  BOTTOM w2.54: JP11.2 129.31,37.67 129.41,37.77 129.41,40.11 129.16,40.36 129.16,44.96
N8241021: length 5.6
  BOTTOM w0.508: C37.2 131.9,68.61 R33.1 U5.3
N8243259: length 7.3
  BOTTOM w0.508: R22.2 116.13,60.78 116.87,61.52 C20.2 R43.1
N8254175: length 23
  BOTTOM w0.762: 70.08,76.3 71.65,76.3 72.72,77.37
  BOTTOM w1.016: 76.35,77.62 T2.1 76.25,77.72 73.08,77.72 72.72,77.37 71.4,78.69 71.4,78.84 ; C27.1 62.46,79.53 66.85,79.53 70.08,76.3
N8276702: length 2.9
  BOTTOM w0.762: R2.2 16.18,29.03 R3.1
N8291038: length 4.4
  BOTTOM w0.762: R45.1 D15.1 C38.2
N8291055: length 19.7
  BOTTOM w0.508: R45.2 141.99,59.82 141.91,59.82 141.35,59.26 134.62,59.26 132.36,61.52 D16.1 131.53,61.52 130.96,60.95 130.96,57.76 131.98,56.74 D17.2
  BOTTOM w0.762: D15.2 141.63,60.27 R45.2
N8302888: length 15.6
  BOTTOM w0.508: U4.3 94.97,57.66 92.51,55.19 JP7.2
N8302918: length 3.1
  BOTTOM w0.508: R14.1 75.16,47.78 D1.1
N8303536: length 25.7
  BOTTOM w0.508: U6.4 95.71,54.71 94.32,53.33 80.86,53.33 79.48,54.71 JP6.2
N8303591: length 18.5
  BOTTOM w0.508: JP2.2 63.98,63.78 64.82,62.94 71.58,62.94 JP6.1 74.75,59.79
N8304521: length 21.4
  BOTTOM w2.54: BR1.4 3.4,8.15 JP13.1 3.4,21.84
N8305228: length 2.3
  BOTTOM w0.508: C37.1 R44.2
N8311567: length 2.3
  BOTTOM w0.508: C21.2 R26.1
N8322201: length 8.6
  BOTTOM w1.016: T2.6 85.85,72.65 86.41,72.09 86.41,67.46 85.27,66.32 D10.2
N80706600: length 1.7
  BOTTOM w0.762: R22.1 D7.2
N82138101: length 3.1
  BOTTOM w0.762: D11.1 73.13,72.29 VR3.1

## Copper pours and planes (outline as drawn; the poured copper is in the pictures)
VCC on BOTTOM: 98.81,72.42 98.35,71.96 96.72,71.96 96.39,72.29 96.39,77.98 97.64,79.22 103.45,79.22 103.45,77.27 99.49,77.27 98.81,76.58
VCC on BOTTOM: 121.46,74.19 124.28,74.19 124.43,74.04 124.43,73.56 124.31,73.43 123.49,73.43 122.71,72.64 122.25,72.64 121.46,73.43
VCCPR on BOTTOM: 82.04,60.93 80.7,59.59 80.67,59.61 80.67,60.96 82.02,60.96
B+ on BOTTOM: 22.56,1.17 22.56,4.24 22.69,4.38 26.56,4.38 36.65,14.48 36.65,32.38 39.98,35.71 55.68,35.71 56.87,34.52 56.87,33.25 60.3,29.82 67.36,29.82 69.14,31.6 69.14,34.06 68.4,34.8 66.95,34.8 66.78,34.98 66.78,35.46 67.08,35.76 69.06,35.76 71.91,32.92 71.91,31.78 70.64,30.51 70.64,30.45 69.9,30.45 67.94,28.5 60.48,28.5 57.18,25.2 57.18,18.29 68.33,7.14 103.45,7.14 104.09,6.5 104.09,5.56 103.38,4.85 67.36,4.85 60.55,11.66 38.23,11.66 27.74,1.17
Net_34 on BOTTOM (solid shape): 145.16,7.87 145.16,1.32 144.4,0.56 140.08,0.56 139.55,1.09 139.55,8.05 140.11,8.61 144.42,8.61
SOURCE on BOTTOM: 57.33,72.62 60.6,72.62 60.6,72.64 61.47,73.51 61.47,72.62 62.15,71.93 62.15,67.16 63.94,65.37 68.26,65.37 68.67,64.96 76.87,64.96 76.9,64.94 82.68,70.71 84.18,70.71 84.68,70.21 84.68,69.44 78.77,63.53 78.77,60.45 78.47,60.16 77.01,60.16 73.16,64.01 67.34,64.01 66.76,64.58 61.81,64.58 59.5,66.89 57.09,66.89 56.39,67.59 56.39,71.68
N5956925 on BOTTOM: outline of 90 points within 55.19,41.99 79.86,57.53
N5957241 on BOTTOM: 59.54,24.79 63.3,24.79 64.62,23.47 64.62,22.58 64.16,22.12 59.97,22.12 59.51,22.58 59.51,24.77
N6214944 on BOTTOM: 63.86,37.64 65.94,37.64 66.17,37.41 66.17,37.01 65.91,36.75 64.82,36.75 64.26,36.2 64.26,34.16 64.85,33.58 66.12,33.58 67.46,32.23 67.46,31.8 66.85,31.19 66.42,31.19 65.23,32.38 63.6,32.38 63.07,32.92 63.07,36.86
N6216380 on BOTTOM: 59.21,37.82 59.92,37.82 61.54,36.2 61.54,34.01 61.06,33.53 59.94,33.53 58.83,34.65 58.83,37.44
N6283849 on BOTTOM: 83.16,36.47 94.13,36.47 94.44,36.17 94.44,32.38 93.8,31.75 85.29,31.75 84.45,30.91 84.45,24.87 76.83,17.25 75.79,17.25 74.83,18.21 74.83,20.22 81.76,27.15 81.76,27.81 81.79,27.81 81.79,35.1
N6939237 on BOTTOM: 66.12,19.56 66.12,27.08 66.55,27.51 68.1,27.51 68.12,27.48 71.96,27.48 72.82,28.35 72.82,33.99 69.09,37.72 66.95,37.72 66.73,37.95 66.73,38.43 66.98,38.68 69.67,38.68 73.94,34.42 73.94,27.64 72.24,25.93 68.83,25.93 68.3,25.4 68.3,21.23 73.66,15.88 78.97,15.88 81.74,18.64 87.88,18.64 89.26,20.02 94.08,20.02 94.54,19.56 94.54,15.62 94.13,15.21 93.98,15.21 92.28,13.51 72.06,13.51 70.46,15.11 70.46,15.21
N7091362 on BOTTOM: 155.04,43.61 151.38,43.61 150.34,42.57 150.34,40.39 150.14,40.18 141.48,40.18 139.29,42.37 139.29,51.89 136.86,54.33 136.86,55.98 138.56,57.68 138.56,57.76 138.53,57.73 135.03,57.73 132.77,59.99 132.33,59.99 131.9,59.56 131.9,58.9 133.6,57.2 133.6,53.01 132.44,51.84 132.44,38.15 133.91,36.68 142.93,36.68 146.86,32.74 146.86,30.25 145.82,29.21 145.82,28.02 146.74,27.1 152.1,27.1 156.59,31.6 156.59,42.06
N7093005 on BOTTOM: 148.67,55.47 149.25,54.89 154.89,54.89 156.39,53.39 156.39,46.18 154.61,44.4 151.31,44.4 148.69,41.78 147.17,41.78 146.99,41.96 146.99,58.14 148.23,59.39 148.62,59.39 148.67,59.33
N8059193 on BOTTOM: 32.64,74.35 34.11,74.35 34.9,73.56 34.9,65.99 32.13,63.22 32.13,53.97 31.01,52.86 31.01,45.82 26.59,41.4 26.58,41.41 9.87,41.41 8.46,42.82 8.46,42.93 7.67,43.71 7.67,50.04 8.66,51.03 10.24,51.03 11.15,50.11 11.15,45.26 11.8,44.62 24.51,44.62 26.14,46.24 26.14,53.01 26.11,53.04 26.11,61.44 31.93,67.26 31.93,73.63
N8059197 on BOTTOM: 5.33,74.47 16.23,74.47 16.76,73.94 16.76,72.09 16.38,71.7 5.31,71.7 5.18,71.83 5.18,74.32
N8059437 on BOTTOM: 5.99,66.65 20.37,66.65 21.26,65.76 21.26,59.11 20.27,58.12 20.28,58.1 20.28,52.29 21.11,51.46 21.11,48.79 20.6,48.29 18.39,48.29 13.25,53.43 13.25,56.3 17.75,60.81 17.75,62.56 16.54,63.78 5.92,63.78 5.31,64.39 5.31,65.96
N8070276 on BOTTOM: 137.97,66.4 136.91,65.33 136.96,65.28 139.12,65.28 138,66.4
N8070354 on BOTTOM: outline of 116 points within 92.08,49.38 137.49,79.04
N8073568 on BOTTOM: 37.77,47.32 37.77,59.66 40.46,62.36 40.46,74.14 45.44,79.12 45.47,79.12 45.75,79.4 52.78,79.4 53.01,79.17 53.01,76.58 52.68,76.25 47.27,76.25 46.38,75.36 46.38,47.29 52.81,40.87 52.81,40.84 56.85,40.84 56.87,40.82 59.46,40.82 60.68,39.6 62.74,39.6 63.78,40.64 64.77,40.64 65.68,41.55 69.93,41.55 71.91,39.57 77.22,39.57 77.77,39.01 77.77,37.52 77.34,37.08 72.95,37.08 69.47,40.56 66.85,40.56 65.89,39.6 63.98,39.6 62.48,38.1 61.16,38.1 60.71,38.56 60.71,38.58 60.25,39.04 58.78,39.04 57.95,38.21 37.18,38.21 37.11,38.15 32.35,33.38 32.35,26.07 26.59,20.32 26.11,20.32 26.09,20.35 25.04,20.35 24.54,20.85 24.54,22.89 28.8,27.15 28.8,38.35
N8076448 on BOTTOM: 112.14,5.94 134.14,5.94 135.03,5.05 135.03,2.49 133.99,1.45 113.87,1.45 112.14,3.17
N8079055 on BOTTOM: 109.5,60.83 109.55,60.83 110.31,60.07 110.31,58.06 112.06,58.06 112.95,58.95 112.95,60.93 112.9,60.99 109.65,60.99
N8088388 on BOTTOM: 20.24,74.45 27.81,74.45 28.63,73.63 28.63,72.42 27.97,71.76 20.07,71.76 19.46,72.36 19.46,73.66
N8097697 on BOTTOM: 91.67,77.39 93.19,77.39 93.6,76.99 93.6,74.35 92.15,72.9 91.41,72.9 91.06,73.25 91.06,76.78
N8123728 on BOTTOM: 143.87,40.97 145.21,42.32 145.21,54.56 143.38,56.39 137.9,56.39 137.62,56.11 137.62,54.38 140.08,51.92 140.08,42.85 141.96,40.97
N8233629 on BOTTOM: 145.47,15.34 146.71,16.59 146.71,20.35 143.18,23.88 143.18,26.59 143.92,27.33 145.57,27.33 151.16,21.74 151.16,12.19 148.69,9.73 124.28,9.73 117.68,16.33 117.68,22.86 119.43,24.61 126.47,24.61 135.74,15.34
N8233891 on BOTTOM: 141.33,26.37 141.33,24.05 146.08,19.3 146.08,17.37 145.08,16.38 136.45,16.38 127.99,24.84 127.99,26.21 129.24,27.46 140.23,27.46
N8234616 on BOTTOM: 122.99,47.96 123.85,47.09 123.67,46.91 123.67,35.86 128.17,31.37 128.17,31.34 130.68,31.34 134.9,35.56 142.67,35.56 146.1,32.13 146.1,30.84 143.15,27.89 126.52,27.89 125.23,29.17 125.23,29.22 116.41,38.05 116.41,47.45 116.92,47.96
N8234966 on BOTTOM: 131.34,50.44 131.29,50.39 127.05,50.39 125.09,48.44 125.09,35.31 128.05,32.35 128.07,32.36 130.56,32.36 131.34,33.15
N8254175 on BOTTOM: 57.96,80.16 75.56,80.16 77.14,78.59 77.14,76.91 77.11,76.89 73.05,76.89 72.34,76.17 72.34,76.07 72.16,75.9 68.15,75.9 66.4,77.65 62.53,77.65 59.49,74.6 58.17,74.6 57.28,75.49 57.28,79.48

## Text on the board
Ref Des/Silkscreen Bottom: +48V | RTN
Ref Des/Silkscreen Top: JP3 | JP5 | TM | S/N | 1939 | DER-850 | HIPER-LCS | REV A | 180-264V | AC INPUT | NEUTRAL | LINE | ON | OFF | OUTPUT | 48VDC | +48VDC | RTN
User.7: NOTE:FOUR SLOTS AND ONE CUTOUT. | PLEASE IGNORE OR DELETE PINS: | 13   MATERIAL FR4 COPPER 2oz THICKNESS 0.062" | 14. FAB HOUSE LOGO,DATE CODE TO BE IN SILK SCREEN ONLY.DO NOT USE COPPER. | SLOTS | SLOT | CUT OUT
User.9: FIGURE | FINISHED_SIZE | 30.0 | 31.0 | 38.0 | 40.0 | 46.0 | 50.0 | 52.0 | 59.0 | 60.0 | 65.0 | 70.0 | 80.0 | 156.0x40.0 | ROTATION | - | 90.000 | DRILL CHART: TOP to BOTTOM | ALL UNITS ARE IN MILS | PLATED | NONSTANDARD | OTHER | QTY | 46 | 14 | 21 | 17 | 4 | 2 | 9 | 6 | 8 | 7 | 10 | 1 | 147 | TOTAL HOLES:
